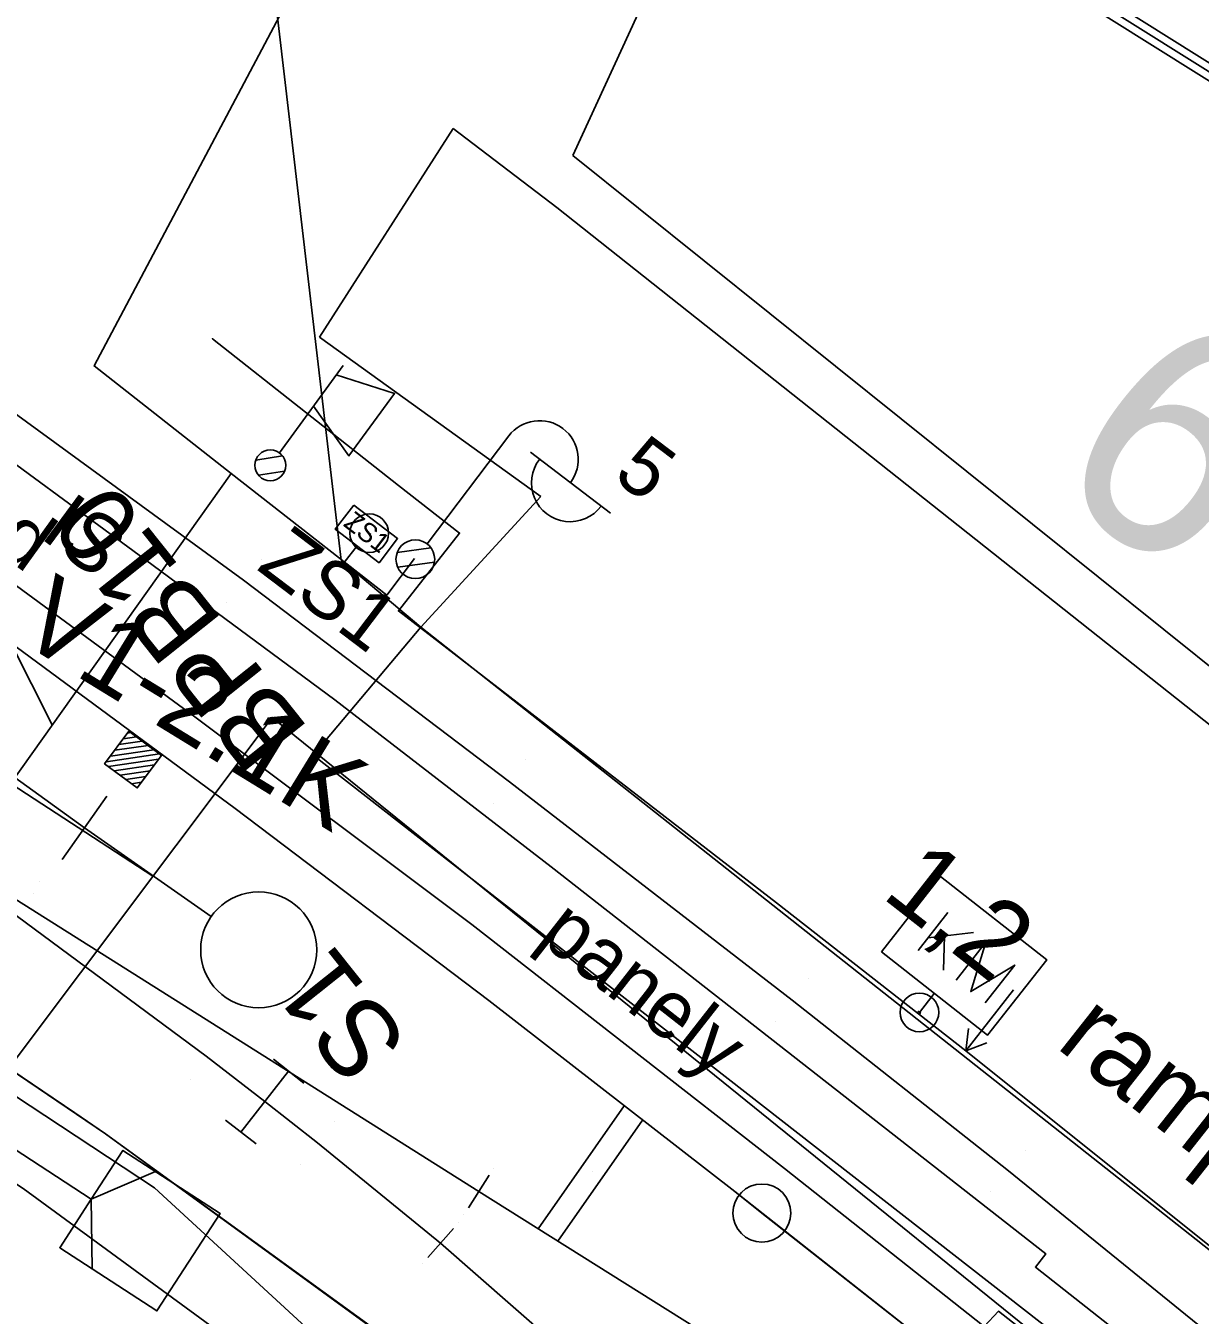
# Model space of a CAD drawing. Extents: x -620624 to -619936, y -1122925 to -1122325.
# Drawn here: x -620312.88 to -620282.51, y -1122684.75 to -1122651.4 of the extents above; entities that cross this region are included whole.
import ezdxf

# ---------------------------------------------------------------- set-up
doc = ezdxf.new("R2010")
doc.units = 0
for name, color, linetype in [('060601_EOV', 7, 'Continuous'), ('060604_ROZVODY_SEE', 7, 'Continuous'), ('POPIS KABELOVÉ TRASY', 7, 'Continuous'), ('PS 06-14-01_trasa_sdělovací_nové', 7, 'Continuous'), ('SEE', 7, 'Continuous'), ('SO 06', 7, 'Continuous'), ('SSZT', 7, 'Continuous'), ('UZEMNĚNÍ', 7, 'Continuous'), ('Vrstva 1', 7, 'Continuous'), ('Vrstva 12', 7, 'Continuous'), ('Vrstva 16', 7, 'Continuous'), ('Vrstva 2', 7, 'Continuous'), ('Vrstva 21', 7, 'Continuous'), ('Vrstva 24', 7, 'Continuous'), ('Vrstva 25', 7, 'Continuous'), ('Vrstva 27', 7, 'Continuous'), ('Vrstva 3', 7, 'Continuous'), ('Vrstva 33', 7, 'Continuous'), ('Vrstva 4', 7, 'Continuous'), ('Vrstva 51', 7, 'Continuous'), ('Vrstva 53', 7, 'Continuous'), ('Vrstva 55', 7, 'Continuous'), ('Vrstva 62', 7, 'Continuous'), ('Vrstva 7', 7, 'Continuous')]:
    doc.layers.add(name, color=color, linetype=linetype)

msp = doc.modelspace()

# ---------------------------------------------------------------- linework, layer by layer
at = {"layer": '060601_EOV'}
msp.add_lwpolyline([(-620235.16, -1122712.242), (-620240.174, -1122718.342), (-620243.025, -1122715.998), (-620248.321, -1122722.765), (-620259.889, -1122713.575), (-620277.713, -1122700.902), (-620282.346, -1122705.302), (-620297.82, -1122689.49), (-620304.222, -1122684.862), (-620310.815, -1122680.061), (-620322.228, -1122672.322), (-620343.182, -1122658.459), (-620368.499, -1122642.897), (-620403.528, -1122620.134)], dxfattribs=at)
at = {"layer": '060604_ROZVODY_SEE'}
msp.add_line((-620304.307, -1122664.856), (-620304.643, -1122665.284), dxfattribs=at)
for points in [[(-620243.025, -1122715.998), (-620248.321, -1122722.765), (-620259.889, -1122713.575), (-620277.713, -1122700.902), (-620282.346, -1122705.302), (-620297.82, -1122689.49), (-620304.222, -1122684.862), (-620310.815, -1122680.061), (-620316.822, -1122675.988), (-620322.228, -1122672.322), (-620326.634, -1122669.408), (-620343.182, -1122658.459), (-620368.499, -1122642.897), (-620403.528, -1122620.134)], [(-620316.822, -1122675.988), (-620307.569, -1122662.984), (-620311.113, -1122660.198), (-620304.112, -1122646.984), (-620307.038, -1122645.433), (-620340.053, -1122630.257)], [(-620302.826, -1122665.182), (-620303.546, -1122666.133), (-620307.569, -1122662.984)]]:
    msp.add_lwpolyline(points, dxfattribs=at)
msp.add_lwpolyline([(-620304.396, -1122663.798), (-620303.263, -1122664.665), (-620303.741, -1122665.29), (-620304.874, -1122664.423)], close=True, dxfattribs=at)
at = {"layer": 'POPIS KABELOVÉ TRASY'}
msp.add_lwpolyline([(-620312.196, -1122669.486), (-620323.97, -1122646.126), (-620330.292, -1122641.833)], dxfattribs=at)
at = {"layer": 'PS 06-14-01_trasa_sdělovací_nové'}
msp.add_lwpolyline([(-620248.321, -1122722.765), (-620259.889, -1122713.575), (-620277.711, -1122700.887), (-620282.346, -1122705.302), (-620297.82, -1122689.49), (-620310.815, -1122680.061), (-620322.228, -1122672.322), (-620343.182, -1122658.459), (-620368.499, -1122642.897), (-620403.528, -1122620.134)], dxfattribs=at)
at = {"layer": 'SEE'}
for points in [[(-620244.518, -1122694.296), (-620246.547, -1122692.66), (-620267.469, -1122718.6), (-620268.222, -1122719.534), (-620284.407, -1122704.62), (-620304.333, -1122686.26), (-620309.55, -1122681.453), (-620327.714, -1122669.483), (-620362.834, -1122646.339), (-620390.254, -1122629.02), (-620403.659, -1122620.327)], [(-620340.053, -1122630.257), (-620307.038, -1122645.433), (-620304.995, -1122662.882), (-620304.721, -1122665.223), (-620302.66, -1122666.96), (-620305.446, -1122670.265), (-620283.044, -1122687.742), (-620274.947, -1122694.711), (-620269.357, -1122688.084), (-620267.489, -1122689.555)]]:
    msp.add_lwpolyline(points, dxfattribs=at)
at = {"layer": 'SO 06'}
msp.add_lwpolyline([(-620298.23, -1122690.946), (-620299.598, -1122691.249), (-620312.943, -1122681.47), (-620333.337, -1122667.924), (-620356.709, -1122652.765), (-620357.203, -1122652.946), (-620404.674, -1122621.82)], dxfattribs=at)
at = {"layer": 'SSZT'}
msp.add_line((-620309.595, -1122673.397), (-620323.304, -1122664.466), dxfattribs=at)
msp.add_lwpolyline([(-620404.277, -1122621.236), (-620363.271, -1122647.563), (-620313.966, -1122679.218), (-620306.51, -1122669.289), (-620273.137, -1122696.274), (-620258.422, -1122709.142), (-620248.072, -1122696.094)], dxfattribs=at)
at = {"layer": 'UZEMNĚNÍ'}
msp.add_line((-620304.307, -1122664.856), (-620304.643, -1122665.284), dxfattribs=at)
msp.add_lwpolyline([(-620302.826, -1122665.182), (-620303.546, -1122666.133), (-620307.569, -1122662.984), (-620311.113, -1122660.198), (-620304.112, -1122646.984), (-620307.038, -1122645.433), (-620340.053, -1122630.257)], dxfattribs=at)
at = {"layer": 'Vrstva 1'}
msp.add_line((-620311.36, -1122672.145), (-620313.165, -1122670.848), dxfattribs=at)
for points in [[(-620402.092, -1122618.019), (-620398.172, -1122620.479), (-620378.269, -1122633.015), (-620362.958, -1122642.66), (-620347.616, -1122652.305), (-620342.456, -1122655.575), (-620322.526, -1122668.083), (-620312.925, -1122674.13), (-620301.163, -1122681.549), (-620292.126, -1122687.227), (-620282.992, -1122692.997), (-620276.394, -1122697.25), (-620266.758, -1122703.956), (-620255.894, -1122712.191)], [(-620348.688, -1122637.935), (-620341.5, -1122642.47), (-620339.854, -1122643.512), (-620333.156, -1122647.798), (-620327.653, -1122651.408), (-620321.139, -1122655.817), (-620314.146, -1122660.717), (-620307.245, -1122665.745), (-620300.366, -1122670.953), (-620293.063, -1122676.601), (-620287.47, -1122681.018), (-620281.24, -1122686.066), (-620276.174, -1122690.251), (-620272.417, -1122693.451), (-620267.757, -1122697.544), (-620266.519, -1122698.689), (-620262.242, -1122702.65), (-620256.103, -1122708.562), (-620249.907, -1122714.621), (-620245.657, -1122718.815), (-620238.557, -1122725.547), (-620230.199, -1122732.623), (-620229.854, -1122732.906)], [(-620339.555, -1122649.372), (-620332.789, -1122653.783), (-620326.854, -1122657.769), (-620323.491, -1122660.075), (-620319.328, -1122662.995), (-620318.623, -1122663.494), (-620316.382, -1122665.099), (-620314.967, -1122666.125), (-620314.061, -1122666.783), (-620307.461, -1122671.648), (-620300.906, -1122676.615), (-620294.546, -1122681.556), (-620287.988, -1122686.712), (-620281.909, -1122691.52)], [(-620339.555, -1122649.372), (-620332.789, -1122653.783), (-620326.854, -1122657.769), (-620323.491, -1122660.075), (-620319.328, -1122662.995), (-620318.623, -1122663.494), (-620316.382, -1122665.099), (-620314.967, -1122666.125), (-620314.061, -1122666.783), (-620307.461, -1122671.648), (-620300.906, -1122676.615), (-620294.546, -1122681.556), (-620293.844, -1122682.108), (-620287.988, -1122686.712), (-620281.909, -1122691.52)], [(-620322.526, -1122668.083), (-620313.097, -1122674.436), (-620308.214, -1122678.053), (-620306.7, -1122679.227), (-620305.337, -1122680.296), (-620302.152, -1122682.886), (-620294.636, -1122689.472), (-620288.443, -1122695.324), (-620284.812, -1122699.019), (-620282.778, -1122701.089), (-620280.313, -1122703.598), (-620275.628, -1122708.447), (-620262.902, -1122721.469), (-620255.487, -1122728.261), (-620248.439, -1122734.187)], [(-620288.271, -1122699.248), (-620297.82, -1122689.49), (-620304.222, -1122684.862), (-620310.815, -1122680.061), (-620311.612, -1122679.521), (-620316.822, -1122675.988)]]:
    msp.add_lwpolyline(points, dxfattribs=at)
at = {"layer": 'Vrstva 12'}
msp.add_line((-620287.336, -1122676.337), (-620288.569, -1122677.912), dxfattribs=at)
for points in [[(-620280.626, -1122684.271), (-620288.569, -1122677.912), (-620293.461, -1122674.083), (-620303.242, -1122666.538), (-620301.662, -1122664.522), (-620303.242, -1122663.293), (-620308.054, -1122659.497), (-620303.242, -1122663.293), (-620301.662, -1122664.522), (-620303.242, -1122666.538), (-620293.461, -1122674.083), (-620288.569, -1122677.912), (-620280.626, -1122684.271)], [(-620288.497, -1122677.333), (-620288.569, -1122677.912), (-620288.025, -1122677.703)]]:
    msp.add_lwpolyline(points, dxfattribs=at)
at = {"layer": 'Vrstva 16'}
msp.add_lwpolyline([(-620268.767, -1122698.19), (-620269.667, -1122699.332), (-620273.339, -1122696.067), (-620280.591, -1122690.258), (-620287.721, -1122684.651), (-620288.092, -1122685.04), (-620293.259, -1122680.96), (-620301.343, -1122674.65), (-620308.503, -1122669.28), (-620315.629, -1122664.052), (-620319.501, -1122661.293), (-620318.339, -1122659.55), (-620317.166, -1122660.468), (-620313.424, -1122663.148), (-620313.111, -1122662.768), (-620309.78, -1122665.216), (-620304.891, -1122668.836), (-620299.292, -1122673.151), (-620286.498, -1122683.168), (-620286.771, -1122683.508), (-620280.456, -1122688.482), (-620273.255, -1122694.212), (-620268.767, -1122698.19)], dxfattribs=at)
at = {"layer": 'Vrstva 2'}
for p, q in [((-620310.248, -1122669.695), (-620310.165, -1122669.683)), ((-620310.58, -1122670.142), (-620309.718, -1122670.015)), ((-620310.469, -1122669.993), (-620309.867, -1122669.904)), ((-620310.358, -1122669.844), (-620310.016, -1122669.793)), ((-620310.801, -1122670.44), (-620309.42, -1122670.236)), ((-620310.69, -1122670.29), (-620309.569, -1122670.126)), ((-620310.74, -1122670.563), (-620309.443, -1122670.372)), ((-620310.591, -1122670.674), (-620309.554, -1122670.521)), ((-620310.442, -1122670.785), (-620309.664, -1122670.67)), ((-620310.293, -1122670.895), (-620309.775, -1122670.819)), ((-620310.144, -1122671.006), (-620309.886, -1122670.968)), ((-620310.786, -1122671.326), (-620311.934, -1122672.964)), ((-620308.085, -1122674.441), (-620311.36, -1122672.145)), ((-620300.897, -1122681.126), (-620301.429, -1122681.972)), ((-620301.822, -1122682.51), (-620302.482, -1122683.262))]:
    msp.add_line(p, q, dxfattribs=at)
for points in [[(-620322.526, -1122668.083), (-620312.925, -1122674.13), (-620301.163, -1122681.549)], [(-620322.526, -1122668.083), (-620313.097, -1122674.436), (-620308.214, -1122678.053), (-620306.7, -1122679.227), (-620305.337, -1122680.296), (-620302.152, -1122682.886)]]:
    msp.add_lwpolyline(points, dxfattribs=at)
msp.add_lwpolyline([(-620310.212, -1122669.647), (-620309.37, -1122670.274), (-620309.996, -1122671.116), (-620310.839, -1122670.49)], close=True, dxfattribs=at)
msp.add_lwpolyline([(-620310.212, -1122669.647), (-620309.37, -1122670.274), (-620309.996, -1122671.116), (-620310.839, -1122670.49)], close=True, dxfattribs=at)
msp.add_circle((-620306.856, -1122675.302), 1.5, dxfattribs=at)
at = {"layer": 'Vrstva 21'}
msp.add_lwpolyline([(-620278.199, -1122655.15), (-620292.229, -1122646.35)], dxfattribs=at)
at = {"layer": 'Vrstva 24'}
msp.add_lwpolyline([(-620290.18, -1122638.043), (-620288.956, -1122635.357), (-620288.746, -1122634.895), (-620288.807, -1122634.799), (-620288.468, -1122634.585), (-620288.293, -1122634.864), (-620288.592, -1122635.523), (-620289.819, -1122638.216), (-620292.2, -1122642.988), (-620293.069, -1122643.428), (-620293.552, -1122643.824), (-620293.341, -1122644.392), (-620293.084, -1122645.144), (-620292.101, -1122646.194), (-620278.093, -1122654.98), (-620278.306, -1122655.319), (-620292.358, -1122646.505), (-620293.435, -1122645.355), (-620293.718, -1122644.527), (-620294.027, -1122643.695), (-620293.289, -1122643.091), (-620292.499, -1122642.691)], close=True, dxfattribs=at)
at = {"layer": 'Vrstva 25'}
for p, q in [((-620302.503, -1122664.801), (-620300.389, -1122662.012)), ((-620299.831, -1122662.435), (-620297.759, -1122664.005)), ((-620304.037, -1122664.496), (-620303.957, -1122664.556)), ((-620303.274, -1122665.028), (-620302.403, -1122664.908)), ((-620303.259, -1122665.404), (-620302.311, -1122665.273))]:
    msp.add_line(p, q, dxfattribs=at)
for centre in [(-620303.997, -1122664.526), (-620302.805, -1122665.2)]:
    msp.add_circle(centre, 0.5, dxfattribs=at)
for centre, start, end in [((-620299.592, -1122662.616), 322.8473, 142.8473), ((-620298.803, -1122663.23), 142.1447, 323.5498)]:
    msp.add_arc(centre, 1, start, end, dxfattribs=at)
at = {"layer": 'Vrstva 3'}
for p, q in [((-620305.689, -1122678.749), (-620306.476, -1122678.132)), ((-620307.317, -1122680.014), (-620306.083, -1122678.44)), ((-620306.924, -1122680.322), (-620307.711, -1122679.705))]:
    msp.add_line(p, q, dxfattribs=at)
at = {"layer": 'Vrstva 33'}
for p, q in [((-620304.673, -1122660.188), (-620306.319, -1122662.447)), ((-620306.93, -1122662.634), (-620306.243, -1122662.526)), ((-620306.86, -1122663.028), (-620306.186, -1122662.922))]:
    msp.add_line(p, q, dxfattribs=at)
msp.add_lwpolyline([(-620304.85, -1122660.43), (-620303.343, -1122660.91), (-620304.521, -1122662.526), (-620305.439, -1122661.239)], dxfattribs=at)
msp.add_circle((-620306.555, -1122662.771), 0.401, dxfattribs=at)
at = {"layer": 'Vrstva 51'}
msp.add_lwpolyline([(-620319.501, -1122661.293), (-620315.629, -1122664.052), (-620308.503, -1122669.28), (-620301.343, -1122674.65), (-620293.259, -1122680.96), (-620288.092, -1122685.04), (-620287.721, -1122684.651), (-620280.591, -1122690.258), (-620273.339, -1122696.067), (-620269.667, -1122699.332)], dxfattribs=at)
at = {"layer": 'Vrstva 53'}
for p, q in [((-620298.73, -1122654.76), (-620296.23, -1122649.3)), ((-620301.83, -1122654.06), (-620305.28, -1122659.46)), ((-620299.15, -1122656.1), (-620301.83, -1122654.06)), ((-620298.73, -1122654.76), (-620265, -1122681.82)), ((-620299.15, -1122656.1), (-620261.22, -1122686.17)), ((-620299.56, -1122663.58), (-620305.28, -1122659.46)), ((-620299.56, -1122663.58), (-620302.66, -1122666.96)), ((-620267.81, -1122694.49), (-620302.66, -1122666.96))]:
    msp.add_line(p, q, dxfattribs=at)
at = {"layer": 'Vrstva 55'}
for p, q in [((-620298.73, -1122654.76), (-620296.23, -1122649.3)), ((-620301.83, -1122654.06), (-620305.28, -1122659.46)), ((-620299.15, -1122656.1), (-620301.83, -1122654.06)), ((-620265, -1122681.82), (-620298.73, -1122654.76)), ((-620261.22, -1122686.17), (-620299.15, -1122656.1)), ((-620305.28, -1122659.46), (-620299.56, -1122663.58)), ((-620299.56, -1122663.58), (-620302.66, -1122666.96)), ((-620302.66, -1122666.96), (-620267.81, -1122694.49))]:
    msp.add_line(p, q, dxfattribs=at)
at = {"layer": 'Vrstva 62'}
for p, q in [((-620306.783, -1122665.199), (-620306.783, -1122665.199)), ((-620307.677, -1122666.314), (-620307.677, -1122666.314)), ((-620299.944, -1122670.391), (-620299.944, -1122670.391)), ((-620300.788, -1122671.515), (-620300.788, -1122671.515)), ((-620312.536, -1122673.534), (-620312.536, -1122673.534)), ((-620312.692, -1122673.835), (-620312.692, -1122673.835)), ((-620292.625, -1122676.047), (-620292.625, -1122676.047)), ((-620293.501, -1122677.156), (-620293.501, -1122677.156)), ((-620307.809, -1122677.461), (-620307.809, -1122677.461)), ((-620308.618, -1122678.645), (-620308.618, -1122678.645)), ((-620306.275, -1122678.641), (-620306.275, -1122678.641)), ((-620307.124, -1122679.813), (-620307.124, -1122679.813)), ((-620304.896, -1122679.744), (-620304.896, -1122679.744)), ((-620287.021, -1122680.479), (-620287.021, -1122680.479)), ((-620305.778, -1122680.848), (-620305.778, -1122680.848)), ((-620300.779, -1122680.954), (-620300.779, -1122680.954)), ((-620287.92, -1122681.558), (-620287.92, -1122681.558)), ((-620301.687, -1122682.347), (-620301.687, -1122682.347)), ((-620301.547, -1122682.144), (-620301.547, -1122682.144)), ((-620302.618, -1122683.425), (-620302.618, -1122683.425))]:
    msp.add_line(p, q, dxfattribs=at)
at = {"layer": 'Vrstva 7'}
for p, q in [((-620289.031, -1122674.335), (-620289.802, -1122675.315)), ((-620288.375, -1122674.851), (-620289.547, -1122674.991)), ((-620289.12, -1122674.94), (-620289.146, -1122675.831)), ((-620289.77, -1122676.92), (-620289.385, -1122676.43)), ((-620289.809, -1122676.889), (-620289.731, -1122676.951)), ((-620299.627, -1122682.514), (-620297.403, -1122679.337)), ((-620299.118, -1122682.834), (-620296.928, -1122679.705)), ((-620311.185, -1122681.748), (-620313.701, -1122680.114)), ((-620298.228, -1122681.039), (-620298.228, -1122681.039))]:
    msp.add_line(p, q, dxfattribs=at)
msp.add_lwpolyline([(-620290.754, -1122675.354), (-620289.22, -1122673.402), (-620286.478, -1122675.557), (-620288.012, -1122677.509)], close=True, dxfattribs=at)
for points in [[(-620288.822, -1122676.086), (-620288.051, -1122675.105), (-620288.443, -1122676.383), (-620287.302, -1122675.694), (-620288.073, -1122676.674)], [(-620311.185, -1122681.748), (-620312.002, -1122683.006), (-620309.487, -1122684.641), (-620307.852, -1122682.125), (-620310.368, -1122680.491), (-620311.185, -1122681.748)], [(-620309.528, -1122681.036), (-620311.185, -1122681.748), (-620311.162, -1122683.552)]]:
    msp.add_lwpolyline(points, dxfattribs=at)
for centre, radius in [((-620289.77, -1122676.92), 0.5), ((-620293.844, -1122682.108), 0.75), ((-620293.844, -1122682.108), 0.75)]:
    msp.add_circle(centre, radius, dxfattribs=at)

# ---------------------------------------------------------------- texts
at = {"layer": '060604_ROZVODY_SEE'}
msp.add_text('ZS1', height=0.5, rotation=322.5799, dxfattribs=at).set_placement((-620304.691, -1122664.322))
at = {"layer": 'Vrstva 12'}
for s, rotation, p in [('1,2', 321.9495, (-620290.78, -1122673.923)), ('rampa', 321.7315, (-620286.274, -1122677.804))]:
    msp.add_text(s, height=2, rotation=rotation, dxfattribs=at).set_placement(p)
at = {"layer": 'Vrstva 16'}
msp.add_text('panely', height=1.5, rotation=321.941, dxfattribs=at).set_placement((-620299.672, -1122675.04))
at = {"layer": 'Vrstva 25'}
for s, rotation, p in [('5', 322.8473, (-620297.732, -1122663.1)), ('ZS1', 322.8711, (-620306.939, -1122665.446))]:
    msp.add_text(s, height=1.5, rotation=rotation, dxfattribs=at).set_placement(p)
at = {"layer": 'Vrstva 27'}
msp.add_text('V1-2.1K', height=2, rotation=328.4879, dxfattribs=at).set_placement((-620313.166, -1122667.242))
at = {"layer": 'Vrstva 3'}
for s, height, rotation, p in [('IS', 1.5, 323.6053, (-620312.548, -1122664.624)), ('BPB10', 2, 128.542, (-620305.526, -1122669.616)), ('S1', 2, 128.542, (-620302.932, -1122677.683))]:
    msp.add_text(s, height=height, rotation=rotation, dxfattribs=at).set_placement(p)
at = {"layer": 'Vrstva 4'}
msp.add_text('Přejezd', height=1.5, rotation=324.2373, dxfattribs=at).set_placement((-620318.371, -1122661.606))
at = {"layer": 'Vrstva 7'}
msp.add_text('63,4', height=6, rotation=321.8255, dxfattribs=at).set_placement((-620286.609, -1122663.084))

doc.saveas('drawing.dxf')
